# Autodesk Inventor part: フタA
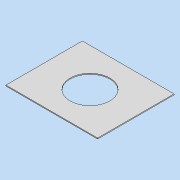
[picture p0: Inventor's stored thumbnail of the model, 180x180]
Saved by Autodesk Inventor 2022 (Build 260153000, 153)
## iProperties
Created: 2021-07
Part Number: フタA
Material: 一般
Document SubType Name: Modeling
Designer: DesignLab
Density: 1 g/cm^3
Appearance: 既定
Author: DesignLab
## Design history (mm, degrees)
sketch "スケッチ1"
  geometry: L1 (0, 0)-(-300, 0); L2 (-300, 0)-(-300, -250); L3 (-300, -250)-(0, -250); L4 (0, -250)-(0, 0)
  constraints: 8 end point, 2 parallel, 1 horizontal, 1 perpendicular
  dimensions: "d0" = 300 distance of L3.end L2.end; "d1" = 250 distance of L2.end L1.end
extrude "押し出し1" new body sketch "スケッチ1" distance "d2" = 3; taper "d3" = 0 deg
sketch "スケッチ2"
  geometry: C1 r 65 at (150, 125); 1 further point
  constraints: 1 centre point
  dimensions: "d4" = 130 diameter of C1; "d5" = 150 horizontal distance of point (0, 0) C1.centre; "d6" = 125 vertical distance of C1.centre point (0, 0)
extrude "押し出し2" cut sketch "スケッチ2" distance "d7" = 3; taper "d8" = 0 deg
node "ソリッド1"
